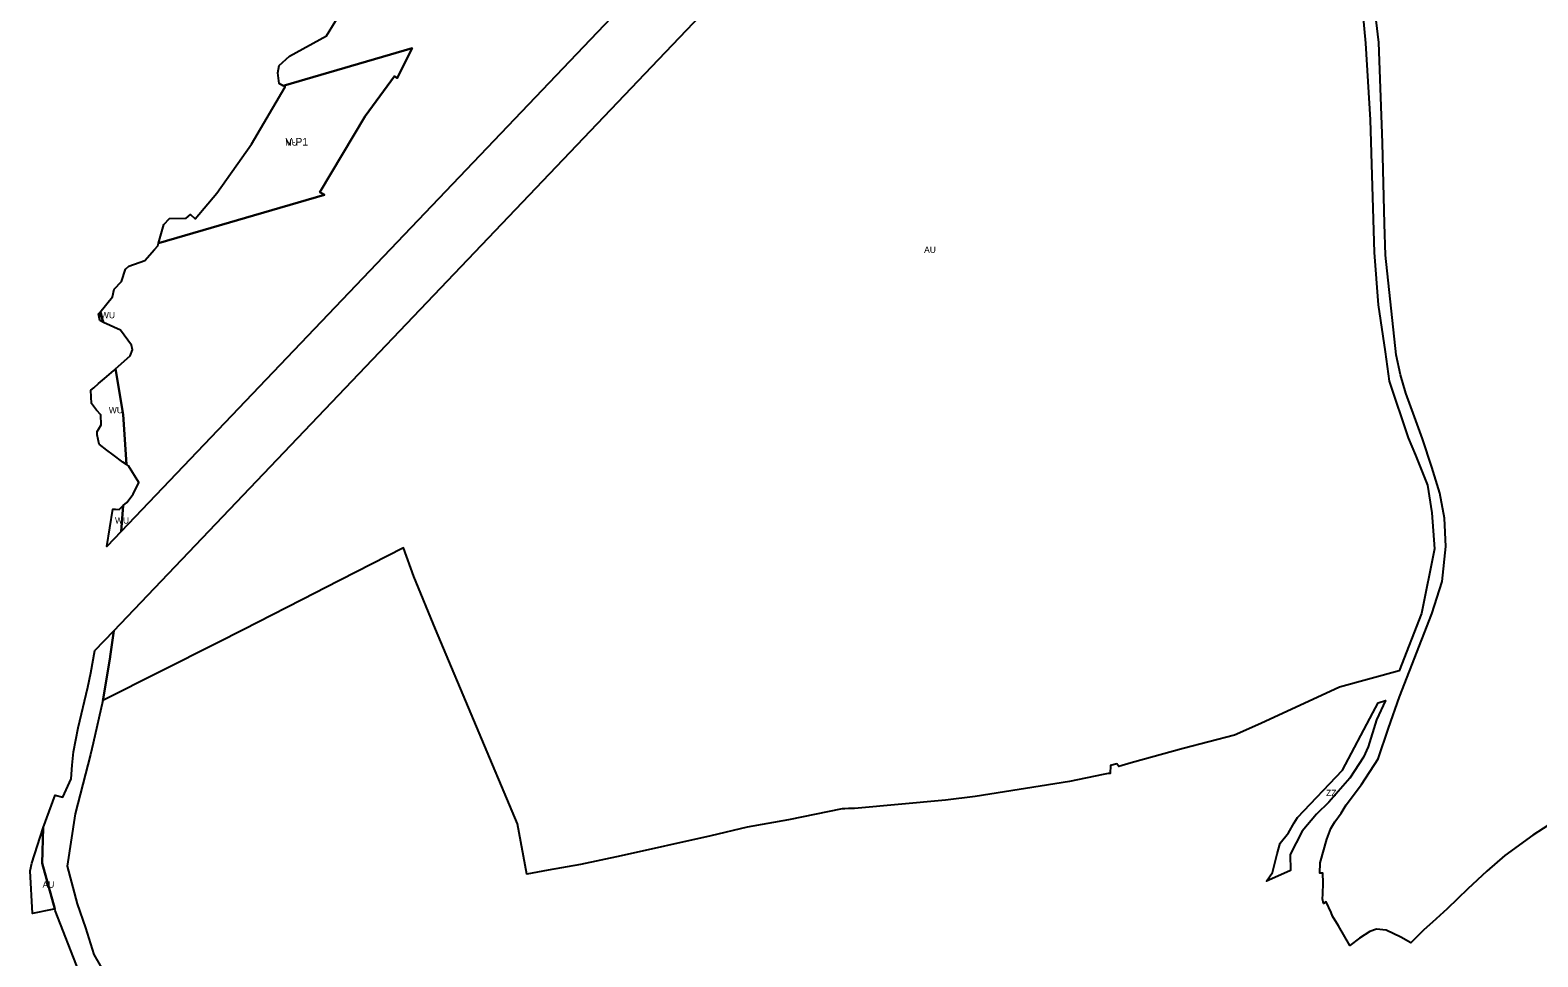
# Model space of a CAD drawing. Extents: x -532067 to -529270, y -1180561 to -1176456.
# Drawn here: x -532067 to -530875, y -1178117 to -1177385 of the extents above; entities that cross this region are included whole.
import ezdxf

# ---------------------------------------------------------------- set-up
doc = ezdxf.new("R2010")
doc.units = 0
for name, color, linetype in [('90630013', 7, 'Continuous'), ('90670013', 7, 'Continuous'), ('90730023', 7, 'Continuous'), ('90750013', 7, 'Continuous'), ('ID_navrh', 7, 'Continuous')]:
    doc.layers.add(name, color=color, linetype=linetype)

msp = doc.modelspace()

# ---------------------------------------------------------------- linework, layer by layer
at = {"layer": '90630013'}
for points in [[(-532012.1683, -1177607.98245), (-532009.3043, -1177615.72645), (-532012.2643, -1177614.29245), (-532013.3873, -1177609.06945)], [(-531993.8163, -1177688.61945), (-531991.0143, -1177728.18545), (-531994.0223, -1177726.17445), (-532001.7103, -1177720.47445), (-532006.5563, -1177716.78645), (-532012.7393, -1177712.09245), (-532014.4103, -1177704.71645), (-532014.4103, -1177702.03445), (-532012.9063, -1177699.85445), (-532011.0683, -1177696.83745), (-532011.4493, -1177688.82745), (-532014.7173, -1177685.24245), (-532018.8013, -1177679.91645), (-532019.2093, -1177669.26445), (-532016.8613, -1177667.42045), (-532013.1853, -1177664.14345), (-532008.3863, -1177660.04645), (-532001.1373, -1177653.79845), (-531999.9123, -1177652.38745)], [(-531993.8613, -1177760.60945), (-531995.3273, -1177780.99745), (-531995.3403, -1177781.01145), (-532006.6183, -1177792.84145), (-532001.9613, -1177763.41645), (-531999.8993, -1177763.41645), (-531996.9543, -1177763.56345)]]:
    msp.add_lwpolyline(points, close=True, dxfattribs=at)
msp.add_lwpolyline([(-532028.7763, -1178128.57945), (-532047.3973, -1178080.58845), (-532047.7273, -1178079.39245), (-532057.7113, -1178043.23045), (-532057.0873, -1178015.23545), (-532047.5703, -1177989.53145), (-532041.3473, -1177991.00045), (-532034.7573, -1177976.55945), (-532034.0503, -1177965.91745), (-532033.0413, -1177955.18945), (-532029.2073, -1177936.36445), (-532021.7413, -1177904.18045), (-532019.3203, -1177892.84545), (-532016.1103, -1177875.26045), (-532001.1503, -1177859.56845), (-532004.0093, -1177879.97745), (-532004.0573, -1177880.31745), (-532009.5583, -1177913.42645), (-532009.8633, -1177914.77145), (-532017.5013, -1177948.46245), (-532019.5363, -1177957.43845), (-532031.7353, -1178004.29445), (-532037.9833, -1178045.77745), (-532030.2473, -1178075.32345), (-532023.5883, -1178094.38545), (-532016.8253, -1178115.38245), (-532006.9563, -1178132.89245)], dxfattribs=at)
at = {"layer": '90670013'}
msp.add_lwpolyline([(-531076.3253, -1178051.44145), (-531089.7823, -1178057.48045), (-531085.1353, -1178050.58445), (-531081.3913, -1178035.78345), (-531079.1893, -1178027.38845), (-531072.5823, -1178019.43645), (-531067.9573, -1178011.48345), (-531065.3143, -1178007.06545), (-531029.8573, -1177969.73145), (-531005.8593, -1177924.40945), (-531001.4993, -1177916.53545), (-530995.8013, -1177914.67845), (-531002.8073, -1177929.87745), (-531009.5663, -1177951.31145), (-531013.3403, -1177959.57045), (-531023.9113, -1177976.13845), (-531040.6493, -1177995.13645), (-531050.3393, -1178004.63545), (-531061.7913, -1178018.11045), (-531071.2613, -1178036.44645), (-531071.0403, -1178049.03745)], close=True, dxfattribs=at)
at = {"layer": '90730023'}
msp.add_lwpolyline([(-531777.1983, -1177422.58145), (-531779.1343, -1177421.02745), (-531802.5663, -1177452.68945), (-531838.3183, -1177512.88145), (-531834.5093, -1177514.79145), (-531965.7373, -1177553.02145), (-531961.7143, -1177538.26845), (-531957.0913, -1177533.56345), (-531944.0663, -1177533.35645), (-531940.5523, -1177530.45245), (-531936.8303, -1177533.77045), (-531919.6713, -1177513.44645), (-531892.1753, -1177474.87245), (-531865.5833, -1177429.45545), (-531867.2833, -1177428.57845), (-531765.2173, -1177398.84445)], close=True, dxfattribs=at)
at = {"layer": '90750013'}
for points in [[(-531013.9583, -1177369.33145), (-531011.5613, -1177394.82245), (-531007.9653, -1177455.65945), (-531004.8483, -1177560.50445), (-531001.7323, -1177601.86645), (-530996.1843, -1177639.00245), (-530992.8723, -1177662.25645), (-530977.8713, -1177707.00545), (-530972.2223, -1177720.68445), (-530962.6133, -1177744.47445), (-530959.2533, -1177766.19445), (-530957.0133, -1177794.65445), (-530967.4663, -1177845.95845), (-530985.0123, -1177891.27045), (-531032.2163, -1177904.22945), (-531094.3663, -1177932.91745), (-531115.2653, -1177942.02045), (-531155.6903, -1177952.50245), (-531196.8973, -1177964.02845), (-531206.6683, -1177966.76145), (-531208.0953, -1177964.79345), (-531213.2693, -1177966.04545), (-531213.4483, -1177972.48845), (-531215.0533, -1177972.48845), (-531219.0823, -1177973.31545), (-531245.5613, -1177978.75145), (-531320.2903, -1177990.65445), (-531343.7213, -1177993.52145), (-531415.7293, -1178000.11345), (-531420.3633, -1177999.98245), (-531423.1153, -1178000.28945), (-531425.3063, -1178000.34745), (-531467.8423, -1178009.01245), (-531500.4653, -1178014.88645), (-531529.1933, -1178021.60045), (-531600.0023, -1178037.41445), (-531632.1983, -1178044.31545), (-531657.8963, -1178048.92645), (-531674.5133, -1178052.02145), (-531681.9353, -1178012.18045), (-531746.9613, -1177858.18645), (-531764.0773, -1177816.58545), (-531772.1393, -1177794.02845), (-531834.6043, -1177825.98245), (-531841.2853, -1177829.40045), (-531898.9523, -1177858.90145), (-531919.1213, -1177869.10445), (-532009.8633, -1177914.77145), (-532009.5583, -1177913.42645), (-532004.0573, -1177880.31745), (-532004.0093, -1177879.97745), (-532001.1503, -1177859.56845), (-531565.1173, -1177402.19045), (-531281.2583, -1177104.43545)], [(-531591.6293, -1177357.53745), (-531995.3273, -1177780.99745), (-531993.8613, -1177760.60945), (-531990.9163, -1177758.09745), (-531985.9083, -1177751.59745), (-531981.3223, -1177742.26745), (-531989.5113, -1177729.19145), (-531991.0143, -1177728.18545), (-531993.8163, -1177688.61945), (-531999.9123, -1177652.38745), (-531988.2743, -1177642.14645), (-531986.3353, -1177637.53845), (-531987.0493, -1177633.64745), (-531995.8293, -1177621.87045), (-532009.3043, -1177615.72645), (-532012.1683, -1177607.98245), (-532002.1733, -1177595.40845), (-532000.9033, -1177589.51945), (-531995.1923, -1177583.47145), (-531992.0183, -1177573.60245), (-531989.3213, -1177571.21545), (-531976.6283, -1177566.75845), (-531968.9693, -1177558.12945), (-531966.3153, -1177555.13945), (-531965.7373, -1177553.02145), (-531834.5093, -1177514.79145), (-531838.3183, -1177512.88145), (-531802.5663, -1177452.68945), (-531779.1343, -1177421.02745), (-531777.1983, -1177422.58145), (-531765.2173, -1177398.84445), (-531867.2833, -1177428.57845), (-531870.4603, -1177426.93945), (-531871.4353, -1177418.41245), (-531870.3203, -1177412.68145), (-531862.3783, -1177405.27345), (-531832.9763, -1177389.05845), (-531818.7133, -1177365.89545)], [(-530863.0883, -1178010.55445), (-530879.3833, -1178021.11145), (-530901.4493, -1178037.11645), (-530915.7083, -1178049.71545), (-530930.8253, -1178063.69245), (-530947.0613, -1178079.33945), (-530958.7383, -1178089.84045), (-530965.5253, -1178095.94445), (-530975.8543, -1178106.22745), (-530983.8033, -1178101.69345), (-530995.3373, -1178096.37845), (-531002.9743, -1178095.44045), (-531008.2403, -1178097.34545), (-531016.4083, -1178102.46645), (-531023.9643, -1178108.40745), (-531032.8833, -1178092.84045), (-531037.6453, -1178085.27745), (-531038.8063, -1178082.35745), (-531042.6983, -1178073.96445), (-531044.8383, -1178075.23345), (-531045.6173, -1178071.42645), (-531045.4223, -1178067.91445), (-531045.1203, -1178058.95245), (-531045.4933, -1178051.07545), (-531047.6113, -1178051.10845), (-531047.5143, -1178043.08645), (-531042.3023, -1178024.23045), (-531039.0233, -1178015.75445), (-531035.8703, -1178010.69345), (-531030.7873, -1178003.65745), (-531026.9673, -1177997.27045), (-531014.8703, -1177980.98445), (-531001.4993, -1177960.86645), (-530993.4503, -1177936.65945), (-530984.6873, -1177911.73145), (-530959.2033, -1177846.27645), (-530950.9863, -1177820.59645), (-530948.1413, -1177793.01545), (-530949.0893, -1177770.50645), (-530952.8823, -1177750.85045), (-530959.2033, -1177730.24345), (-530966.4723, -1177707.73445), (-530969.7203, -1177699.04445), (-530972.9683, -1177690.35345), (-530979.8183, -1177671.66545), (-530983.9283, -1177657.09845), (-530987.4903, -1177641.43345), (-530995.7103, -1177562.55645), (-530996.6723, -1177537.90445), (-530998.3133, -1177473.68045), (-531001.1283, -1177394.47345), (-531005.7623, -1177354.41745)]]:
    msp.add_lwpolyline(points, dxfattribs=at)
msp.add_lwpolyline([(-532049.9763, -1178080.01345), (-532065.3253, -1178083.07645), (-532067.2883, -1178049.38945), (-532065.8723, -1178043.32545), (-532057.0873, -1178015.23545), (-532057.7113, -1178043.23045), (-532047.7273, -1178079.39245)], close=True, dxfattribs=at)

# ---------------------------------------------------------------- texts
at = {"layer": '90630013'}
for rotation, p in [(0.00000004, (-532011.3458, -1177612.47192)), (0.00000002, (-532005.1118, -1177687.55495)), (0.00000001, (-532000.2398, -1177774.7836))]:
    msp.add_text('WU', height=5, rotation=rotation, dxfattribs=at).set_placement(p)
at = {"layer": '90670013'}
msp.add_text('ZZ', height=5, rotation=0.00000003, dxfattribs=at).set_placement((-531042.7918, -1177990.29369))
at = {"layer": '90730023'}
msp.add_text('NU', height=5, rotation=359.99999999, dxfattribs=at).set_placement((-531865.4773, -1177475.93276))
at = {"layer": '90750013'}
for rotation, p in [(359.99999996, (-531360.56466, -1177560.77545)), (359.99999998, (-532057.5078, -1178062.74197))]:
    msp.add_text('AU', height=5, rotation=rotation, dxfattribs=at).set_placement(p)
at = {"layer": 'ID_navrh'}
msp.add_text('V-P1', height=6, rotation=0.00000005, dxfattribs=at).set_placement((-531865.4773, -1177475.93276))

doc.saveas('drawing.dxf')
